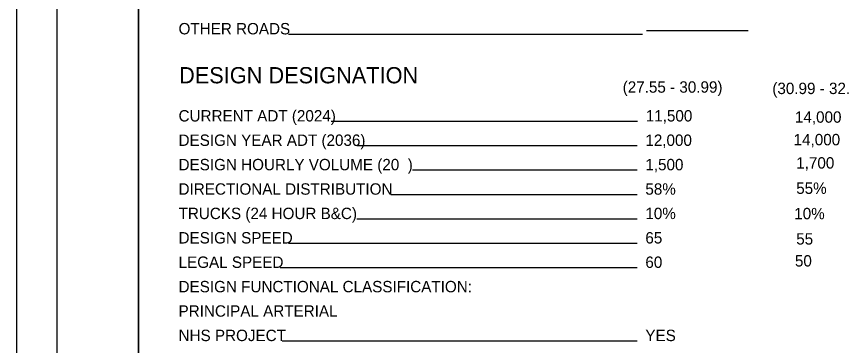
# Model space of a CAD drawing. Extents: x 0 to 34, y 0 to 22.
# Drawn here: x 0 to 10.15, y 7.05 to 11.1 of the extents above; entities that cross this region are included whole.
import ezdxf

# ---------------------------------------------------------------- set-up
doc = ezdxf.new("R2010")
doc.units = 0
for name, color, linetype in [('Default', 7, 'Continuous'), ('SH_Border', 7, 'Continuous'), ('SH_Cut_Line', 7, 'Continuous'), ('SH_Data', 7, 'Continuous'), ('SH_Text', 7, 'Continuous')]:
    doc.layers.add(name, color=color, linetype=linetype)

msp = doc.modelspace()

# ---------------------------------------------------------------- linework, layer by layer
at = {"layer": 'SH_Border'}
for points in [[(0.5, 21.5), (1.5, 21.5), (1.5, 0.5), (0.5, 0.5)], [(1.5, 21.5), (33.5, 21.5), (33.5, 0.5), (1.5, 0.5)]]:
    msp.add_lwpolyline(points, close=True, dxfattribs=at)
at = {"layer": 'SH_Cut_Line'}
msp.add_lwpolyline([(0, 0), (34, 0), (34, 22), (0, 22)], close=True, dxfattribs=at)
at = {"layer": 'SH_Data'}
for p, q in [((7.7, 10.877), (3.347, 10.877)), ((9, 10.922), (7.75, 10.922)), ((7.642, 9.806), (3.871, 9.806)), ((7.637, 9.506), (4.189, 9.506)), ((7.637, 9.206), (4.872, 9.206)), ((7.637, 8.906), (4.604, 8.906)), ((7.637, 8.606), (4.189, 8.606)), ((7.637, 8.306), (3.346, 8.306)), ((7.637, 8.006), (3.242, 8.006)), ((7.637, 7.106), (3.267, 7.106))]:
    msp.add_line(p, q, dxfattribs=at)

# ---------------------------------------------------------------- texts
at = {"layer": 'Default'}
for s, p in [('(27.55 - 30.99)', (7.458, 10.16)), ('(30.99 - 32.92)', (9.299, 10.143)), ('14,000', (9.577, 9.791)), ('14,000', (9.561, 9.513)), ('1,700', (9.593, 9.227)), ('55%', (9.593, 8.916)), ('10%', (9.569, 8.604)), ('55', (9.593, 8.293)), ('50', (9.577, 8.023))]:
    msp.add_text(s, height=0.14, dxfattribs=at).set_placement(p)
at = {"layer": 'SH_Data'}
msp.add_text('DESIGN DESIGNATION', height=0.2, dxfattribs=at).set_placement((2, 10.275))
at = {"layer": 'SH_Text'}
for s, p in [('OTHER ROADS', (1.994, 10.877)), ('CURRENT ADT (2024)', (1.994, 9.806)), ('11,500', (7.742, 9.806)), ('DESIGN YEAR ADT (2036)', (1.994, 9.506)), ('12,000', (7.737, 9.506)), ('DESIGN HOURLY VOLUME (20  )', (1.994, 9.206)), ('1,500', (7.737, 9.206)), ('DIRECTIONAL DISTRIBUTION', (1.994, 8.906)), ('58%', (7.737, 8.906)), ('TRUCKS (24 HOUR B&C)', (1.994, 8.606)), ('10%', (7.737, 8.606)), ('DESIGN SPEED', (1.994, 8.306)), ('65', (7.737, 8.306)), ('LEGAL SPEED', (1.994, 8.006)), ('60', (7.737, 8.006)), ('DESIGN FUNCTIONAL CLASSIFICATION:', (1.994, 7.706)), ('PRINCIPAL ARTERIAL', (1.994, 7.406)), ('NHS PROJECT', (1.994, 7.106)), ('YES', (7.737, 7.106))]:
    msp.add_text(s, height=0.14, dxfattribs=at).set_placement(p)

doc.saveas('drawing.dxf')
